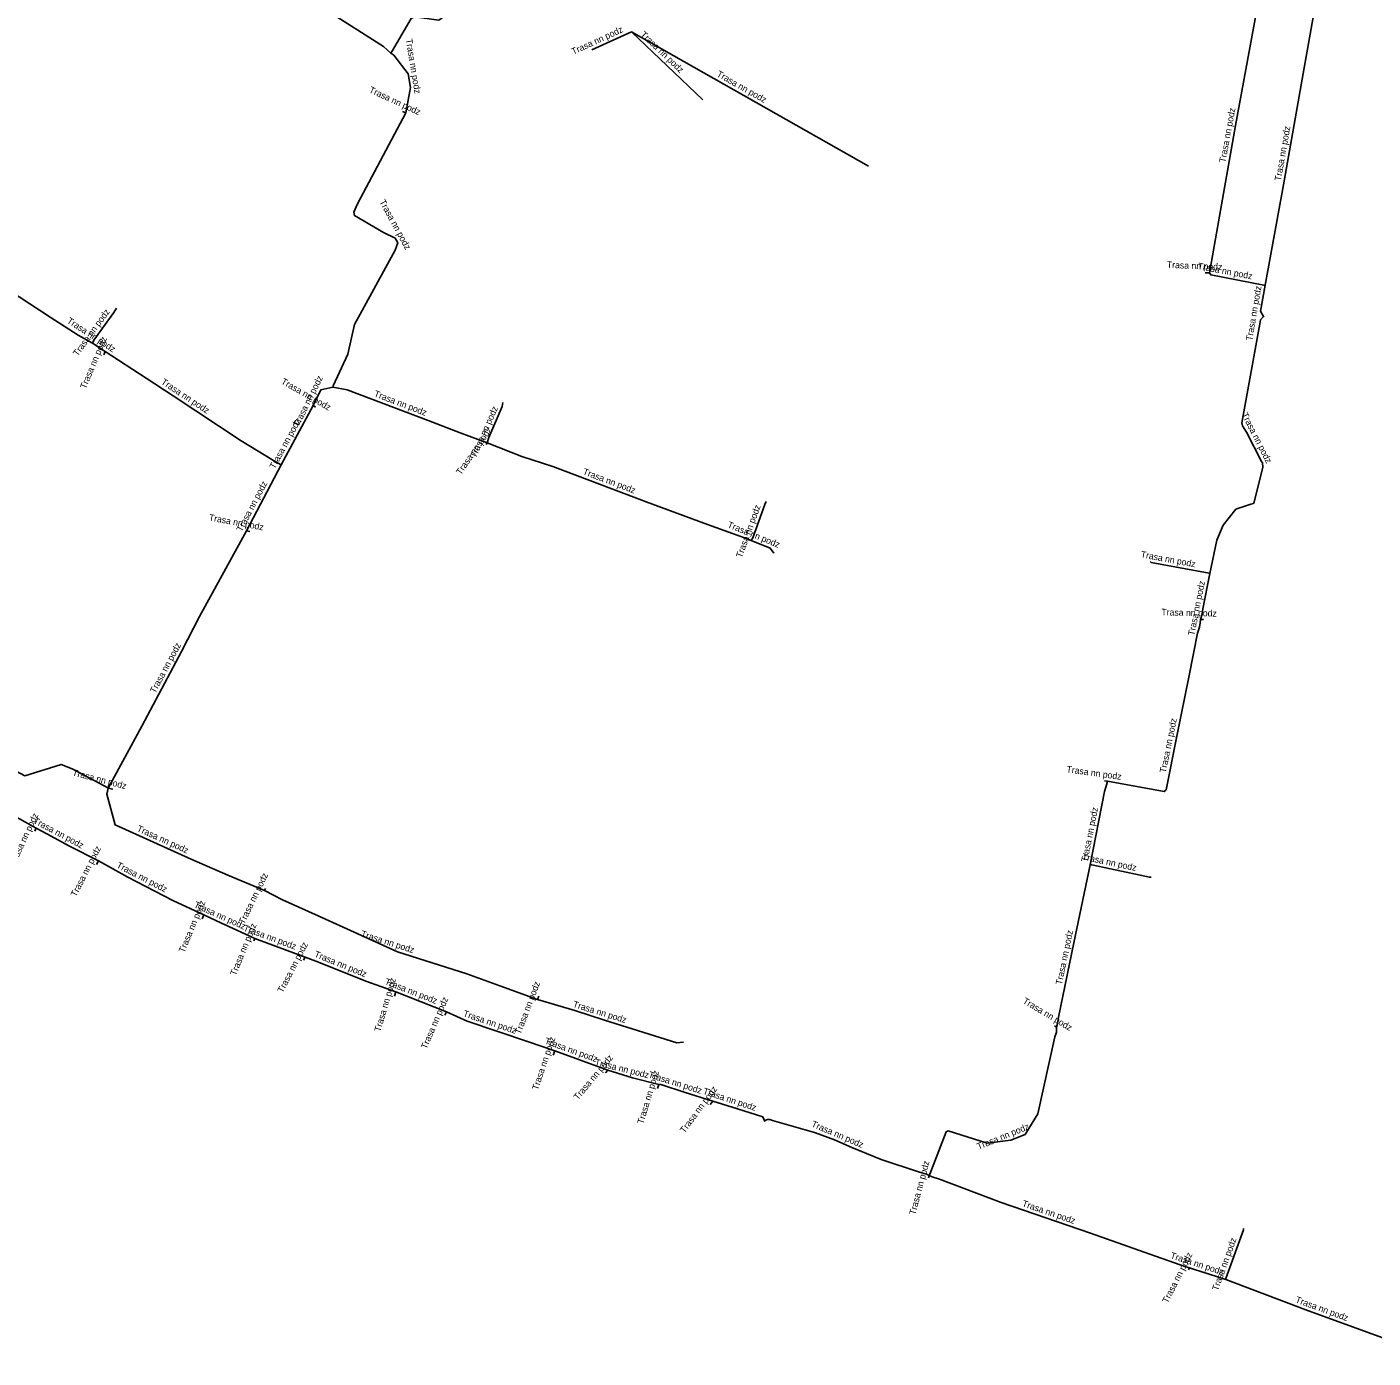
# Model space of a CAD drawing. Extents: x -737281 to -735046, y -1033441 to -1031241.
# Drawn here: x -736080.5 to -735873, y -1032962.2 to -1032757.1 of the extents above; entities that cross this region are included whole.
import ezdxf

# ---------------------------------------------------------------- set-up
doc = ezdxf.new("R2010")
doc.units = 0
doc.layers.add('Level 11', color=7, linetype='Continuous')
doc.layers.add('Level 20', color=7, linetype='Continuous')

msp = doc.modelspace()

# ---------------------------------------------------------------- linework, layer by layer
at = {"layer": 'Level 11'}
for p, q in [((-735987.3, -1032757.8), (-735993.4, -1032760.6)), ((-735987.3, -1032757.8), (-735950.8, -1032778.5)), ((-735987.3, -1032757.8), (-735976.3, -1032768.3)), ((-736022.09, -1032770.32), (-736022.58, -1032770.1)), ((-735898.22, -1032794.97), (-735898.9, -1032794.94)), ((-736070.38, -1032805.8), (-736068.41, -1032807.09)), ((-736068.41, -1032807.09), (-736068.61, -1032807.57)), ((-736041.31, -1032824.52), (-736036.38, -1032815.42)), ((-736036.38, -1032815.42), (-736035.98, -1032815.65)), ((-736009.53, -1032821.16), (-736009.71, -1032821.42)), ((-736041.31, -1032824.52), (-736046.65, -1032834.69)), ((-736046.65, -1032834.69), (-736046.14, -1032834.79)), ((-735899.61, -1032848.36), (-735899.16, -1032848.38)), ((-736067.92, -1032874.36), (-736067.21, -1032874.54)), ((-735913.93, -1032873.31), (-735914.39, -1032873.25)), ((-736089.47, -1032874.75), (-736079.04, -1032880.51)), ((-736079.04, -1032880.51), (-736079.27, -1032880.98)), ((-736069.44, -1032885.55), (-736069.73, -1032886.1)), ((-736043.88, -1032890.14), (-736043.71, -1032889.8)), ((-736053.2, -1032893.9), (-736053.45, -1032894.51)), ((-736045.36, -1032897.51), (-736045.51, -1032897.89)), ((-736045.36, -1032897.51), (-736037.57, -1032900.38)), ((-736037.57, -1032900.38), (-736037.84, -1032900.89)), ((-736023.64, -1032905.76), (-736023.83, -1032906.41)), ((-736023.64, -1032905.76), (-736015.83, -1032908.81)), ((-736001.8, -1032906.95), (-736001.58, -1032906.39)), ((-736015.83, -1032908.81), (-736016.05, -1032909.34)), ((-735921.81, -1032911.17), (-735922.12, -1032910.98)), ((-735999.13, -1032914.83), (-735999.36, -1032915.51)), ((-735999.13, -1032914.83), (-735990.95, -1032917.79)), ((-735990.95, -1032917.79), (-735991.31, -1032918.22)), ((-735983.09, -1032920), (-735983.29, -1032920.66)), ((-735974.78, -1032922.59), (-735975.17, -1032923.11)), ((-735941.43, -1032934.07), (-735941.52, -1032934.39)), ((-735901.31, -1032948.26), (-735901.47, -1032948.59))]:
    msp.add_line(p, q, dxfattribs=at)
for points in [[(-735988.55, -1032729.46), (-735988.46, -1032729.96), (-735988.45, -1032730.43), (-735991.98, -1032737.38), (-735992.23, -1032737.87), (-735992.52, -1032738.35), (-735993.9, -1032741.15), (-735994.44, -1032741.59), (-736004.59, -1032737.11), (-736004.87, -1032737.43), (-736007.93, -1032743.94), (-736012.91, -1032753.1), (-736016.99, -1032756.02), (-736020.75, -1032755.53), (-736021.28, -1032755.77), (-736024.14, -1032760.7), (-736024.37, -1032761.13)], [(-736024.37, -1032761.13), (-736025.5, -1032760.07), (-736034.38, -1032754.42), (-736038.82, -1032751.58), (-736046.02, -1032747.23)], [(-735890.04, -1032748.91), (-735890.41, -1032751.59), (-735894.21, -1032772.25), (-735898.22, -1032794.97)], [(-735889.66, -1032796.84), (-735886.83, -1032781.41), (-735883.81, -1032764.22), (-735881.77, -1032752.65)], [(-736024.37, -1032761.13), (-736023.92, -1032761.43), (-736021.72, -1032764.32), (-736021.38, -1032766.42), (-736022.09, -1032770.32)], [(-736033.33, -1032812.57), (-736033.27, -1032812.35), (-736031, -1032807.5), (-736029.98, -1032802.9), (-736023.74, -1032791.47), (-736023.31, -1032790.34), (-736023.7, -1032789.63), (-736025.54, -1032788.76), (-736030.01, -1032786.14), (-736030.11, -1032785.6), (-736029.5, -1032784.33), (-736022.09, -1032770.32)], [(-736106.49, -1032782.62), (-736101.12, -1032786.15), (-736096.79, -1032788.83), (-736084.84, -1032796.59), (-736076.86, -1032801.78), (-736072.57, -1032804.55), (-736070.38, -1032805.8)], [(-735898.22, -1032794.97), (-735898.05, -1032795.28), (-735889.85, -1032796.84), (-735889.66, -1032796.84)], [(-735889.66, -1032796.84), (-735890.36, -1032800.88), (-735889.84, -1032801.77)], [(-736066.65, -1032800.42), (-736067.06, -1032801.06), (-736070.16, -1032805.32), (-736070.38, -1032805.8)], [(-735898.16, -1032841.3), (-735897.12, -1032836.14), (-735896.13, -1032833.86), (-735894.16, -1032831.36), (-735891.89, -1032830.59), (-735891.45, -1032830.48), (-735891.35, -1032830.27), (-735890.01, -1032824.91), (-735890.09, -1032824.25), (-735890.2, -1032824.03), (-735892.51, -1032819.49), (-735893.14, -1032818.51), (-735893.23, -1032818.06), (-735890.58, -1032803.38), (-735890.53, -1032803.15), (-735890.37, -1032802.18), (-735889.9, -1032801.71), (-735889.84, -1032801.77)], [(-736068.41, -1032807.09), (-736062.09, -1032811.17), (-736057.92, -1032813.9), (-736047.44, -1032820.82), (-736042.49, -1032823.85), (-736041.31, -1032824.52)], [(-736036.38, -1032815.42), (-736035.18, -1032812.99), (-736033.33, -1032812.57)], [(-736033.33, -1032812.57), (-736031.1, -1032812.97), (-736018.66, -1032817.72), (-736013.7, -1032819.6), (-736009.53, -1032821.16)], [(-736007.12, -1032814.92), (-736007.22, -1032815.57), (-736009.31, -1032820.35), (-736009.53, -1032821.16)], [(-736009.53, -1032821.16), (-736004.18, -1032823.27), (-735999.41, -1032824.8), (-735985.02, -1032830.23), (-735975.58, -1032833.72), (-735970.47, -1032835.58), (-735968.86, -1032836.21)], [(-735966.56, -1032830.19), (-735966.76, -1032830.67), (-735968.63, -1032835.81), (-735968.86, -1032836.21)], [(-736046.65, -1032834.69), (-736053.85, -1032847.9), (-736056.64, -1032853.31), (-736062.78, -1032864.79), (-736067.92, -1032874.36)], [(-735965.36, -1032838.14), (-735965.91, -1032837.4), (-735968.86, -1032836.21)], [(-735907.38, -1032839.46), (-735907.2, -1032839.61), (-735898.28, -1032841.25), (-735898.16, -1032841.3)], [(-735899.61, -1032848.36), (-735899.34, -1032847.54), (-735899.24, -1032846.72), (-735898.16, -1032841.3)], [(-735899.61, -1032848.36), (-735899.67, -1032848.89), (-735899.8, -1032849.58), (-735900.09, -1032850.48), (-735901.39, -1032857.02), (-735903.28, -1032866.33), (-735904.89, -1032874.61), (-735905.23, -1032874.87), (-735913.93, -1032873.31)], [(-736067.92, -1032874.36), (-736068.45, -1032874.06), (-736073.49, -1032871.39), (-736075.2, -1032870.7), (-736080.81, -1032872.44), (-736088.13, -1032868.54), (-736093.22, -1032865.61), (-736098.06, -1032862.92)], [(-736043.88, -1032890.14), (-736049.48, -1032887.79), (-736055.06, -1032885.38), (-736066.87, -1032879.99), (-736068.17, -1032875.28), (-736067.92, -1032874.36)], [(-735913.93, -1032873.31), (-735914.17, -1032874.06), (-735914.39, -1032874.88), (-735916.6, -1032886.16)], [(-736079.04, -1032880.51), (-736077.4, -1032881.41), (-736073.89, -1032883.28), (-736069.44, -1032885.55)], [(-736069.44, -1032885.55), (-736064.9, -1032888.07), (-736057.96, -1032891.65), (-736053.2, -1032893.9)], [(-735921.81, -1032911.17), (-735921.68, -1032910.61), (-735921.49, -1032909.63), (-735919.12, -1032898.2), (-735916.6, -1032886.16)], [(-735907.21, -1032888.09), (-735907.5, -1032888.1), (-735916.36, -1032886.2), (-735916.6, -1032886.16)], [(-736043.88, -1032890.14), (-736041.1, -1032891.57), (-736035.59, -1032894.03), (-736023.38, -1032899.57), (-736012.69, -1032902.99), (-736007.58, -1032904.83), (-736001.8, -1032906.95)], [(-736053.2, -1032893.9), (-736050.49, -1032895.17), (-736046.89, -1032896.8), (-736045.36, -1032897.51)], [(-736037.57, -1032900.38), (-736035.52, -1032901.15), (-736028.26, -1032904.1), (-736023.64, -1032905.76)], [(-735979.28, -1032913.51), (-735980.32, -1032913.58), (-735991.47, -1032910.11), (-735996.03, -1032908.62), (-736001.8, -1032906.95)], [(-736015.83, -1032908.81), (-736012.63, -1032910.26), (-736003.15, -1032913.47), (-735999.13, -1032914.83)], [(-735941.43, -1032934.07), (-735941.35, -1032933.82), (-735938.8, -1032927.3), (-735938.51, -1032927.16), (-735932.52, -1032929.07), (-735928.84, -1032928.6), (-735926.65, -1032927.72), (-735924.67, -1032924.55), (-735922.06, -1032912.69), (-735921.82, -1032911.95), (-735921.81, -1032911.17)], [(-735990.95, -1032917.79), (-735987.16, -1032918.98), (-735983.09, -1032920)], [(-735983.09, -1032920), (-735982.8, -1032920.03), (-735979.03, -1032921.25), (-735974.78, -1032922.59)], [(-735974.78, -1032922.59), (-735970.96, -1032923.75), (-735967.07, -1032925.02), (-735966.74, -1032925.7)], [(-735966.74, -1032925.7), (-735966.75, -1032925.55), (-735966.36, -1032925.4), (-735965.97, -1032925.42), (-735965.58, -1032925.56), (-735959.11, -1032927.42), (-735958.93, -1032927.46), (-735956.04, -1032928.56), (-735953.37, -1032929.71), (-735948.85, -1032931.59), (-735942.92, -1032933.55), (-735941.83, -1032933.84), (-735941.43, -1032934.07)], [(-735901.31, -1032948.26), (-735901.87, -1032948.1), (-735902.76, -1032947.79), (-735908.3, -1032945.84), (-735916.59, -1032942.94), (-735930.35, -1032938.19), (-735939.86, -1032934.59), (-735940.96, -1032934.24), (-735941.43, -1032934.07)], [(-735893.02, -1032942.19), (-735893.02, -1032942.43), (-735895.7, -1032949.93), (-735895.72, -1032950.09)], [(-735901.31, -1032948.26), (-735900.53, -1032948.53), (-735899.59, -1032948.84), (-735895.72, -1032950.09)], [(-735862.93, -1032962.18), (-735863.52, -1032962.04), (-735864.53, -1032961.65), (-735871.67, -1032959.03), (-735883.41, -1032954.72), (-735895.72, -1032950.09)]]:
    msp.add_lwpolyline(points, dxfattribs=at)

# ---------------------------------------------------------------- texts
at = {"layer": 'Level 20'}
for rotation, p in [(24.6559, (-735996.27, -1032761.37)), (316.3322, (-735986, -1032758.35)), (279.2356, (-736022.08, -1032758.98)), (330.4414, (-735974.27, -1032764.61)), (335.1196, (-736027.83, -1032767.11)), (79.5805, (-735895.78, -1032778.03)), (80.0578, (-735887.24, -1032780.86)), (298.5596, (-736026.19, -1032784)), (357.6421, (-735904.82, -1032794.19)), (349.1804, (-735900.11, -1032794.37)), (80.2461, (-735891.66, -1032805.48)), (326.8754, (-736074.39, -1032802.59)), (54.0262, (-736072.64, -1032807.89)), (67.2359, (-736071.4, -1032812.93)), (326.5442, (-736059.88, -1032812)), (330.2239, (-736041.39, -1032811.98)), (63.776, (-736038.59, -1032818.77)), (339.1147, (-736027.07, -1032813.97)), (66.316, (-736011.28, -1032823.6)), (61.5658, (-736042.27, -1032825.26)), (296.9479, (-735893.32, -1032816.79)), (55.3827, (-736013.6, -1032826.18)), (339.2888, (-735994.89, -1032825.97)), (62.2728, (-736047.35, -1032834.94)), (69.9918, (-735970.3, -1032838.95)), (349.4885, (-736052.48, -1032833.1)), (337.9582, (-735972.6, -1032834.15)), (349.5601, (-735908.88, -1032838.79)), (78.7449, (-735900.58, -1032850.91)), (358.5903, (-735905.66, -1032847.72)), (61.9055, (-736060.69, -1032859.83)), (78.5326, (-735904.96, -1032872.07)), (345.4684, (-736073.53, -1032872.39)), (351.9571, (-735920.32, -1032871.9)), (64.7524, (-736082.29, -1032886.22)), (78.8983, (-735917.04, -1032885.79)), (331.8664, (-736079.58, -1032879.68)), (335.4837, (-736063.61, -1032880.93)), (62.8167, (-736072.9, -1032891.19)), (347.9101, (-735917.95, -1032885.35)), (332.736, (-736066.76, -1032886.55)), (64.1703, (-736046.99, -1032895.41)), (67.3935, (-736056.21, -1032899.81)), (335.6375, (-736054.81, -1032892.67)), (67.8097, (-736048.27, -1032903.34)), (339.7786, (-736047.19, -1032896.31)), (342.2137, (-736029.09, -1032897.21)), (78.3022, (-735920.98, -1032904.72)), (62.6318, (-736041.04, -1032905.99)), (337.8903, (-736036.27, -1032900.31)), (73.5381, (-736026, -1032911.97)), (338.6869, (-736025.41, -1032904.54)), (69.2184, (-736004.39, -1032912.37)), (66.7093, (-736018.88, -1032914.65)), (342.7606, (-735996.41, -1032908.06)), (329.1189, (-735927.11, -1032907.42)), (341.2935, (-736013.33, -1032909.49)), (71.4897, (-736001.71, -1032920.97)), (340.0963, (-736000.78, -1032913.7)), (50.0764, (-735995.55, -1032922.5)), (346.02, (-735993.03, -1032917.01)), (73.1657, (-735985.49, -1032926.2)), (342.5892, (-735984.78, -1032918.92)), (53.3909, (-735979.13, -1032927.6)), (341.8697, (-735976.37, -1032921.45)), (336.8506, (-735959.67, -1032926.47)), (22.0084, (-735933.83, -1032930.08)), (75.1346, (-735943.57, -1032940.18)), (340.9427, (-735927.19, -1032938.75)), (70.3433, (-735896.93, -1032951.89)), (63.2263, (-735904.67, -1032953.81)), (342.1615, (-735904.35, -1032946.79)), (339.8577, (-735885.08, -1032953.57))]:
    msp.add_text('Trasa nn podz', height=1, rotation=rotation, dxfattribs=at).set_placement(p)

doc.saveas('drawing.dxf')
